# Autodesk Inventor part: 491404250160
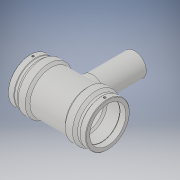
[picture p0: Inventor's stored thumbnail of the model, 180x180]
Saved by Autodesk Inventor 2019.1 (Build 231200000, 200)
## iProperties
Created: 2017-06
Part Number: 491404250160
Material: Generic
Description: PLASSON REDUCING TEE 250x160x250
Document SubType Name: Modeling
Designer: KIM
Mass: 5000.41 g
Surface Area: 5471.45 cm^2
Volume: 5000.41 cm^3
Density: 1 g/cm^3
Appearance: Default
Author: KIM
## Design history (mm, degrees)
derived "491404.ipt"
feature "Solid1::491404.ipt"
tag "TaggingFeature1"
body "Solid1"
other parameters: "d0" = 538, "d2" = 326, "d3" = 129, "d4" = 107.6, "d5" = 293.4, "d6" = 237.5, "d8" = 168 deg, "d10" = 51.6, "d11" = 17.2, "d13" = 538, "d14" = 17.6296, "d17" = 225, "d19" = 3.52592, "d20" = 168 deg, "d22" = 303.18, "d23" = 326, "d25" = 135 deg, "d26" = 376.6, "d29" = 152, "d30" = 15, "d31" = 215.2, "d34" = 5 deg, "d35" = 15, "d39" = 5 deg, "d41" = 4, "d42" = 14, "d43" = 0, "d45" = 4, "d46" = 6, "d47" = 0, "d48" = -455, "d51" = 0, "d52" = 128, "d54" = 0, "d55" = 293.4, "d56" = 326, "d57" = 188.3, "d58" = 135 deg, "d59" = 129, "d60" = 129, "d61" = 135 deg, "d62" = 455, "d72" = 244.79, "d73" = 122.395, "d74" = -455, "d75" = 168, "d77" = 0, "d78" = 128, "d80" = 0, "d82" = 292, "d83" = 0, "d84" = 3, "d85" = 0, "d86" = 43, "d87" = 297.1164, "d88" = 17.2, "d89" = 3, "d90" = 0, "L_" = 538, "L_1" = 129, "D_" = 326, "A_" = 152, "d_2" = 12, "H_" = 455
